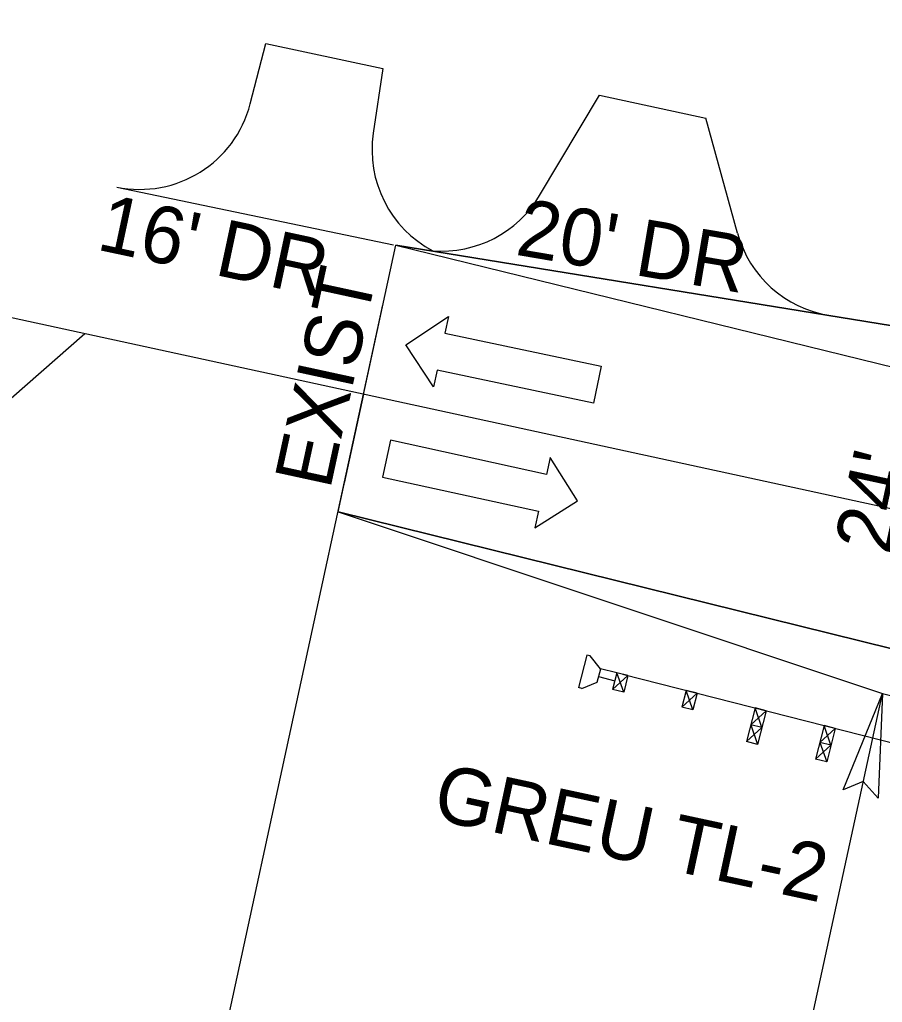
# Model space of a CAD drawing. Extents: x 1762196 to 1766326, y 709922 to 713142.
# Drawn here: x 1762656 to 1762731.7, y 712608.6 to 712694.8 of the extents above; entities that cross this region are included whole.
import ezdxf

# ---------------------------------------------------------------- set-up
doc = ezdxf.new("R2010")
doc.units = 0
for name, color, linetype in [('Old_Level_3', 7, 'Continuous'), ('Prop Dimension', 7, 'Continuous'), ('Prop EOT', 7, 'Continuous'), ('Prop Guardrail Anchor Unit CELL', 7, 'Continuous'), ('Prop Horizontal Alignment', 7, 'Continuous'), ('Prop Horizontal Alignment Station Label', 7, 'Continuous'), ('Prop Horizontal Alignment Tick Large', 7, 'Continuous'), ('Prop Lane Arrow CELL', 7, 'Continuous'), ('Prop Paved Shoulder', 7, 'Continuous'), ('Prop Shade Medium', 7, 'Continuous'), ('Prop Structure Anchor Unit CELL', 7, 'Continuous'), ('Prop Terminator CELL', 7, 'Continuous')]:
    doc.layers.add(name, color=color, linetype=linetype)

msp = doc.modelspace()

# ---------------------------------------------------------------- linework, layer by layer
at = {"layer": 'Old_Level_3'}
for p, q in [((1762676.244, 712687.404), (1762677.606, 712692.698)), ((1762677.606, 712692.698), (1762687.869, 712690.491)), ((1762687.869, 712690.491), (1762687.024, 712684.83)), ((1762701.601, 712679.356), (1762706.858, 712688.169)), ((1762706.858, 712688.169), (1762716.189, 712686.145)), ((1762718.953, 712676.071), (1762716.189, 712686.145)), ((1762664.535, 712680.103), (1762688.802, 712675.04))]:
    msp.add_line(p, q, dxfattribs=at)
for centre, start, end in [((1762666.559, 712689.896), 258.32012, 345.56851), ((1762696.915, 712683.355), 171.51459, 242.20944), ((1762693.013, 712684.479), 265.641, 329.18357), ((1762728.596, 712678.717), 195.34156, 260.80091)]:
    msp.add_arc(centre, 10, start, end, dxfattribs=at)
at = {"layer": 'Prop Dimension'}
msp.add_line((1762708.966, 712531.153), (1762731.651, 712635.719), dxfattribs=at)
at = {"layer": 'Prop EOT'}
msp.add_line((1762683.942, 712651.641), (1762689.009, 712674.997), dxfattribs=at)
for points in [[(1762689.009, 712674.997), (1762737.587, 712663.084), (1762954.282, 712624.26)], [(1762683.942, 712651.641), (1762732.499, 712639.629), (1762945.802, 712585.169)]]:
    msp.add_lwpolyline(points, dxfattribs=at)
at = {"layer": 'Prop Guardrail Anchor Unit CELL'}
for p, q in [((1762705.731, 712639.08), (1762705.007, 712636.231)), ((1762706.028, 712639.005), (1762705.731, 712639.08)), ((1762706.956, 712637.881), (1762706.028, 712639.005)), ((1762706.655, 712636.695), (1762706.958, 712637.881)), ((1762706.78, 712637.183), (1762708.205, 712636.823)), ((1762708.383, 712637.52), (1762706.956, 712637.881)), ((1762708.385, 712637.53), (1762708.009, 712636.058)), ((1762709.354, 712637.282), (1762708.009, 712636.059)), ((1762709.354, 712637.282), (1762708.385, 712637.53)), ((1762708.978, 712635.811), (1762708.385, 712637.53)), ((1762708.87, 712637.406), (1762733.092, 712631.221)), ((1762709.354, 712637.282), (1762708.979, 712635.811)), ((1762705.305, 712636.155), (1762706.655, 712636.695)), ((1762705.305, 712636.155), (1762705.007, 712636.231)), ((1762708.979, 712635.811), (1762708.009, 712636.058)), ((1762714.441, 712635.983), (1762714.065, 712634.512)), ((1762715.41, 712635.736), (1762714.065, 712634.512)), ((1762715.41, 712635.736), (1762714.441, 712635.983)), ((1762715.034, 712634.265), (1762714.441, 712635.983)), ((1762715.41, 712635.736), (1762715.034, 712634.265)), ((1762715.034, 712634.265), (1762714.065, 712634.512)), ((1762720.496, 712634.437), (1762719.746, 712631.496)), ((1762721.466, 712634.19), (1762720.12, 712632.966)), ((1762721.466, 712634.19), (1762720.496, 712634.437)), ((1762721.09, 712632.719), (1762720.496, 712634.437)), ((1762721.466, 712634.19), (1762720.715, 712631.249)), ((1762721.09, 712632.719), (1762720.12, 712632.966)), ((1762720.12, 712632.966), (1762720.715, 712631.249)), ((1762726.552, 712632.891), (1762725.801, 712629.95)), ((1762727.521, 712632.644), (1762726.552, 712632.891)), ((1762727.145, 712631.173), (1762726.552, 712632.891)), ((1762719.746, 712631.496), (1762721.09, 712632.719)), ((1762727.521, 712632.644), (1762726.176, 712631.42)), ((1762727.521, 712632.644), (1762726.771, 712629.702)), ((1762720.715, 712631.249), (1762719.746, 712631.496)), ((1762725.801, 712629.95), (1762727.145, 712631.173)), ((1762727.145, 712631.173), (1762726.176, 712631.42)), ((1762726.176, 712631.42), (1762726.771, 712629.702)), ((1762726.771, 712629.702), (1762725.801, 712629.95))]:
    msp.add_line(p, q, dxfattribs=at)
at = {"layer": 'Prop Horizontal Alignment'}
msp.add_line((1762197.546, 712767.962), (1763046.054, 712583.885), dxfattribs=at)
at = {"layer": 'Prop Horizontal Alignment Station Label'}
for p, q in [((1762568.578, 712585.932), (1762661.748, 712667.257)), ((1762651.31, 712501.226), (1762686.18, 712661.957))]:
    msp.add_line(p, q, dxfattribs=at)
at = {"layer": 'Prop Horizontal Alignment Tick Large'}
for q in [(1762687.876, 712669.775), (1762684.484, 712654.139)]:
    msp.add_line((1762686.18, 712661.957), q, dxfattribs=at)
at = {"layer": 'Prop Lane Arrow CELL'}
for p, q in [((1762689.877, 712666.279), (1762693.621, 712668.757)), ((1762693.621, 712668.757), (1762693.311, 712667.29)), ((1762693.311, 712667.29), (1762707.007, 712664.391)), ((1762692.317, 712662.594), (1762689.877, 712666.279)), ((1762692.627, 712664.062), (1762692.317, 712662.594)), ((1762706.324, 712661.163), (1762692.627, 712664.062)), ((1762707.007, 712664.391), (1762706.324, 712661.163)), ((1762688.531, 712657.903), (1762687.826, 712654.679)), ((1762702.208, 712654.915), (1762688.531, 712657.903)), ((1762702.528, 712656.381), (1762702.208, 712654.915)), ((1762704.923, 712652.582), (1762702.528, 712656.381)), ((1762687.826, 712654.679), (1762701.504, 712651.691)), ((1762701.184, 712650.226), (1762704.923, 712652.582)), ((1762701.504, 712651.691), (1762701.184, 712650.226))]:
    msp.add_line(p, q, dxfattribs=at)
at = {"layer": 'Prop Paved Shoulder'}
for p, q in [((1762689.009, 712674.997), (1762738.435, 712666.993)), ((1762683.942, 712651.641), (1762731.651, 712635.72))]:
    msp.add_line(p, q, dxfattribs=at)
msp.add_spline([(1762731.651, 712635.72), (1762732.612, 712635.475), (1762733.573, 712635.23), (1762734.533, 712634.984), (1762735.494, 712634.739), (1762736.455, 712634.494), (1762737.416, 712634.248), (1762738.377, 712634.003), (1762739.338, 712633.758), (1762740.298, 712633.513), (1762741.259, 712633.267), (1762742.22, 712633.022), (1762743.181, 712632.777), (1762744.142, 712632.531), (1762745.102, 712632.286), (1762746.063, 712632.041), (1762747.024, 712631.795), (1762747.985, 712631.55), (1762748.946, 712631.305), (1762749.907, 712631.059), (1762750.867, 712630.814), (1762751.828, 712630.569), (1762752.789, 712630.323), (1762753.75, 712630.078), (1762754.711, 712629.833), (1762755.671, 712629.587), (1762756.632, 712629.342), (1762757.593, 712629.097), (1762758.554, 712628.852), (1762759.515, 712628.606), (1762760.476, 712628.361), (1762761.436, 712628.116), (1762762.397, 712627.87), (1762763.358, 712627.625), (1762764.319, 712627.38), (1762765.28, 712627.134), (1762766.241, 712626.889), (1762767.201, 712626.644), (1762768.162, 712626.398), (1762769.123, 712626.153), (1762770.084, 712625.908), (1762771.045, 712625.662), (1762772.005, 712625.417), (1762772.966, 712625.172), (1762773.927, 712624.926), (1762774.888, 712624.681), (1762775.849, 712624.436), (1762776.81, 712624.19), (1762777.77, 712623.945), (1762778.731, 712623.7), (1762779.692, 712623.455), (1762780.653, 712623.209), (1762781.614, 712622.964), (1762782.575, 712622.719), (1762783.535, 712622.473), (1762784.496, 712622.228), (1762785.457, 712621.983), (1762786.418, 712621.737), (1762787.379, 712621.492), (1762788.339, 712621.247), (1762789.3, 712621.001), (1762790.261, 712620.756), (1762791.222, 712620.511), (1762792.183, 712620.265), (1762793.144, 712620.02), (1762794.104, 712619.775), (1762795.065, 712619.529), (1762796.026, 712619.284), (1762796.987, 712619.039), (1762797.948, 712618.794), (1762798.909, 712618.548), (1762799.869, 712618.303), (1762800.83, 712618.058), (1762801.791, 712617.812), (1762802.752, 712617.567)], degree=3, dxfattribs=at)
at = {"layer": 'Prop Shade Medium'}
for p, q in [((1762738.435, 712666.993), (1762689.009, 712674.997)), ((1762683.942, 712651.641), (1762731.651, 712635.72)), ((1762683.942, 712651.641), (1762731.651, 712635.72)), ((1762731.651, 712635.72), (1762732.608, 712635.476))]:
    msp.add_line(p, q, dxfattribs=at)
for points in [[(1762689.009, 712674.997), (1762737.587, 712663.084), (1762737.587, 712663.084)], [(1762945.802, 712585.169), (1762732.499, 712639.629), (1762683.942, 712651.641)], [(1762945.802, 712585.169), (1762732.499, 712639.629), (1762683.942, 712651.641)]]:
    msp.add_lwpolyline(points, dxfattribs=at)
at = {"layer": 'Prop Terminator CELL'}
msp.add_lwpolyline([(1762728.228, 712627.252), (1762731.651, 712635.719), (1762731.296, 712626.536), (1762729.976, 712627.999)], close=True, dxfattribs=at)

# ---------------------------------------------------------------- texts
at = {"layer": 'Prop Dimension'}
for s, rotation, p in [("16' DR", 347.94298, (1762662.659, 712674.642)), ("20' DR", 350.35227, (1762699.386, 712674.187)), ('EXIST', 77.75984, (1762683.229, 712653.488)), ("24'", 77.75984, (1762732.294, 712647.766))]:
    msp.add_text(s, height=5, rotation=rotation, dxfattribs=at).set_placement(p)
at = {"layer": 'Prop Structure Anchor Unit CELL'}
msp.add_text('GREU TL-2', height=5, rotation=347.86395, dxfattribs=at).set_placement((1762692.07, 712624.727))

doc.saveas('drawing.dxf')
